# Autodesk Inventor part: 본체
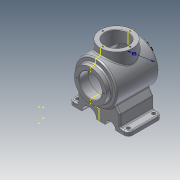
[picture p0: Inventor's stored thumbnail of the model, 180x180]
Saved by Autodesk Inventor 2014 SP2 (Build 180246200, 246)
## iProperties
Created: 2018-08
Part Number: 본체
Material: 알루미늄 6061
Document SubType Name: Modeling
Designer: 거성
Density: 2.71 g/cm^3
Appearance: 알루미늄 - 평지
Mass: 1903.75 g
Surface Area: 1094.31 cm^2
Volume: 702.492 cm^3
Author: 거성
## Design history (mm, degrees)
sketch "스케치1"
  geometry: L1 (0, 60)-(0, -60); L2 (0, 60)-(38, 60); L3 (38, 60)-(38, 48); L4 (38, 48)-(50, 48); L5 (50, 48)-(50, -52); A1 r 232 centre (-11.435, 171.718) between (0, -60) and (50, -52); 2 further points
  constraints: 10 end point, 3 perpendicular, 2 point on circle, 1 centre point, 1 coincident, 1 midpoint, 1 parallel, 1 vertical
  dimensions: "d0" = 120 distance of L1.start L1.end; "d2" = 76 diameter of L3 L1; "d4" = 12 distance of L2.end L3.end; "d22" = 100 distance of L4.end L5.end; "d23" = 232 radius of A1; "d24" = 100 diameter of L5 L1
revolve "회전1" sketch "스케치1" stored, may be unused: angle "d6" = 90 deg
sketch "스케치2" dims "d8" = 65
  geometry: C1 r 38 at (0, 0) reference; C2 r 27 at (0, 0); 2 further points
  constraints: 2 coincident, 2 vertical alignment, 1 centre point, 2 other
  dimensions: "d7" = 54 diameter of C2
extrude "돌출1" cut sketch "스케치2" distance "d9" = 22; taper "d10" = 0 deg
hole "구멍1" sketch "스케치2" diameter "d11" = 3.242; stored, may be unused: countersink angle "d15" = 90 deg, drill point angle "d17" = 118 deg; dims "d12" = 8, "d13" = 4, "d14" = 2, "d16" = 10
node "작업 평면1"
sketch "스케치3"
  geometry: L1 (50, 48)-(50, -52) reference; L2 (-50, -52)-(50, -52) reference; L3 (-50, -52)-(50, -52) reference; L4 (-50, 48)-(-50, -52) reference; L5 (0, -49.674)-(0, 38.326); L6 (0, 38.326)-(40, 38.326); L7 (40, 38.326)-(40, -43.225); A1 r 232 centre (-11.435, 171.718) between (0, -60) and (50, -52) reference; A2 r 232 centre (11.435, 171.718) between (-50, -52) and (0, -60) reference; A3 r 232 centre (-16.787, 181.718) between (0, -49.674) and (40, -43.225); 3 further points
  constraints: 6 end point, 2 point on circle, 1 centre point, 1 coincident, 1 perpendicular
  dimensions: "d89" = 88 distance of L5.start L5.end; "d91" = 232 radius of A3; "d92" = 10 vertical distance of A1.centre A3.centre; "d108" = 80 diameter of L7 L5
  node "투영된 루프1"
node "작업 평면2"
sketch "스케치4" dims "d31" = 65
  geometry: L1 (-50, 48)-(50, 48) reference; C1 r 38 at (0, -2); C2 r 27 at (0, -2); 2 further points
  constraints: 2 centre point, 2 coincident, 1 vertical alignment, 2 other
  dimensions: "d30" = 76 diameter of C1; "d32" = 54 diameter of C2; "d107" = 50 distance from line of L1 C1.centre
extrude "돌출2" join sketch "스케치4" stored distance "d33" = 22; taper "d34" = 0 deg
extrude "돌출3" cut sketch "스케치4" distance "d35" = 50; taper "d36" = 0 deg
hole "구멍2" sketch "스케치4" diameter "d37" = 3.242; stored, may be unused: countersink angle "d41" = 90 deg, drill point angle "d43" = 118 deg; dims "d38" = 8, "d39" = 4, "d40" = 2, "d42" = 10
node "작업 평면3"
sketch "스케치5"
  geometry: L1 (-39.739, -30.345)-(-50, -45); L2 (-50, -45)-(-50, -72); L3 (-50, -72)-(-70, -72); L4 (-70, -72)-(-70, -82); L5 (70, -82)-(70, -72); L6 (70, -72)-(50, -72); L7 (50, -72)-(50, -45); L8 (50, -45)-(39.739, -30.345); L9 (-70, -82)-(-40, -82); L10 (-15, -82)-(5, -82); L11 (40, -82)-(70, -82); C1 r 38 at (0, 0) reference; A1 r 50 centre (0, 0) between (-39.739, -30.345) and (39.739, -30.345) reference; A2 r 12.5 centre (-27.5, -82) between (-15, -82) and (-40, -82); A3 r 17.5 centre (22.5, -82) between (40, -82) and (5, -82); 5 further points
  constraints: 22 end point, 9 perpendicular, 6 point on circle, 3 midpoint, 2 centre point, 2 horizontal alignment, 2 parallel, 1 point on line, 1 vertical, 1 vertical alignment
  dimensions: "d48" = 35 deg angle of L1 L4; "d50" = 20 distance of L2.end L3.end; "d52" = 10 distance of L3.end L4.end; "d61" = 140 distance of L4.end L5.start; "d62" = 20 distance of L5.end L6.end; "d63" = 10 distance of L5.start L5.end; "d64" = 35 deg angle of L5 L8; "d65" = 25 diameter of A2; "d66" = 35 diameter of A3; "d67" = 27.5 distance of point (0, -82) A2.centre; "d68" = 22.5 distance of point (0, -82) A3.centre; "d69" = 27 distance of L1.end L2.end; "d70" = 82 distance from line of C1.centre L9; "d71" = 42.5 distance of L4.end A2.centre; "d72" = 47.5 distance of L5.start A3.centre; "d73" = 22.5 distance of A2.centre point (-5, -82)
extrude "돌출4" join sketch "스케치5" stored distance "d75" = 80; taper "d76" = 0 deg
node "작업 평면4"
fillet "모깎기1" dims "d79" = 3
fillet "모깎기2" dims "d80" = 3
fillet "모깎기3" dims "d81" = 3
fillet "모깎기5" dims "d83" = 10
fillet "모깎기6" dims "d84" = 10
node "작업 평면5"
sketch "스케치7"
  geometry: L1 (38, -38)-(-38, -38) reference; 1 further point
revolve "회전3" stored, may be unused: angle "d93" = 90 deg
fillet "모깎기8" dims "d94" = 3
chamfer "모따기1" distance "d95" = 1; stored, may be unused: second distance "d96" = 2, angle "d97" = 45 deg
node "작업 평면7"
sketch "스케치8"
  geometry: C1 r 4 at (0, 7); C2 r 4 at (0, 67); A1 r 7 centre (0, 67) between (0, 74) and (-7, 67) reference; A2 r 7 centre (0, 7) between (-7, 7) and (0, 0) reference; 1 further point
  constraints: 2 centre point, 2 coincident
  dimensions: "d98" = 8 diameter of C1; "d99" = 8 diameter of C2
extrude "돌출5" cut sketch "스케치8" stored distance "d100" = 80; taper "d101" = 0 deg
node "작업 평면6"
sketch "스케치9"
  geometry: C1 r 4 at (10, -7); C2 r 4 at (10, -67); A1 r 7 centre (10, -67) between (10, -74) and (17, -67) reference; A2 r 7 centre (10, -7) between (17, -7) and (10, 0) reference; 1 further point
  constraints: 2 centre point, 2 coincident
  dimensions: "d102" = 8 diameter of C1; "d103" = 8 diameter of C2
extrude "돌출6" cut sketch "스케치9" distance "d104" = 80; taper "d105" = 0 deg
fillet "모깎기9" dims "d106" = 3
node "작업 평면8"
node "작업 평면9"
sketch "스케치11"
  geometry: L1 (-34.121, 50)-(-32.5, 49.026) reference; L2 (-32.5, 49.026)-(-30.879, 50) reference; L3 (-30.879, 50)-(-30.879, 60) reference; L4 (-30.879, 60)-(-28, 60) reference; L5 (-28, 60)-(-27, 59) reference; L6 (-27, 59)-(-27, 38.326) reference; L7 (-27, 38.326)-(-37, 38.326) reference; L8 (-40, 35.326)-(-40, -40.876) reference; L9 (40, -40.876)-(40, -29) reference; L10 (40, -29)-(64, -29) reference; L11 (64, -29)-(65, -30) reference; L12 (65, -30)-(65, -32.879) reference; L13 (65, -32.879)-(55, -32.879) reference; L14 (55, -32.879)-(54.026, -34.5) reference; L15 (54.026, -34.5)-(55, -36.121) reference; L16 (55, -36.121)-(65, -36.121) reference; L17 (65, -36.121)-(65, -40) reference; L18 (65, -40)-(53, -40) reference; L19 (50, -43)-(50, -49.701) reference; L20 (-50, -49.701)-(-50, -43) reference; L21 (-53, -40)-(-82, -40) reference; L22 (-82, -40)-(-82, 40) reference; L23 (-82, 40)-(-53, 40) reference; L24 (-50, 43)-(-50, 45) reference; L25 (-47, 48)-(-41, 48) reference; L26 (-38, 51)-(-38, 60) reference; L27 (-38, 60)-(-34.121, 60) reference; L28 (-34.121, 60)-(-34.121, 50) reference; L29 (32.5, 49.026)-(34.121, 50) reference; L30 (34.121, 50)-(34.121, 60) reference; L31 (34.121, 60)-(38, 60) reference; L32 (38, 60)-(38, 51) reference; L33 (41, 48)-(47, 48) reference; L34 (50, 45)-(50, 39) reference; L35 (53, 36)-(65, 36) reference; L36 (65, 36)-(65, 32.121) reference; L37 (65, 32.121)-(55, 32.121) reference; L38 (55, 32.121)-(54.026, 30.5) reference; L39 (54.026, 30.5)-(55, 28.879) reference; L40 (55, 28.879)-(65, 28.879) reference; L41 (65, 28.879)-(65, 26) reference; L42 (65, 26)-(64, 25) reference; L43 (64, 25)-(40, 25) reference; L44 (40, 25)-(40, 35.326) reference; L45 (37, 38.326)-(27, 38.326) reference; L46 (27, 38.326)-(27, 59) reference; L47 (27, 59)-(28, 60) reference; L48 (28, 60)-(30.879, 60) reference; L49 (30.879, 60)-(30.879, 50) reference; L50 (30.879, 50)-(32.5, 49.026) reference; L51 (0, 0)-(24.076, -57.548); A1 r 3 centre (-37, 35.326) between (-37, 38.326) and (-40, 35.326) reference; A2 r 3 centre (-37, -40.876) between (-40, -40.876) and (-37.705, -43.792) reference; A3 r 232 centre (16.787, 181.718) between (-37.705, -43.792) and (0, -49.674) reference; A4 r 232 centre (-16.787, 181.718) between (0, -49.674) and (37.705, -43.792) reference; A5 r 3 centre (37, -40.876) between (37.705, -43.792) and (40, -40.876) reference; A6 r 3 centre (47, -49.701) between (47.766, -52.602) and (50, -49.701) reference; A7 r 232 centre (-11.435, 171.718) between (0, -60) and (47.766, -52.602) reference; A8 r 232 centre (11.435, 171.718) between (-47.766, -52.602) and (0, -60) reference; A9 r 3 centre (-47, -49.701) between (-50, -49.701) and (-47.766, -52.602) reference; A10 r 3 centre (-53, -43) between (-50, -43) and (-53, -40) reference; A11 r 3 centre (-53, 43) between (-53, 40) and (-50, 43) reference; A12 r 3 centre (-47, 45) between (-47, 48) and (-50, 45) reference; A13 r 3 centre (-41, 51) between (-41, 48) and (-38, 51) reference; A14 r 3 centre (41, 51) between (38, 51) and (41, 48) reference; A15 r 3 centre (47, 45) between (50, 45) and (47, 48) reference; A16 r 3 centre (37, 35.326) between (40, 35.326) and (37, 38.326) reference
  constraints: 2 end point, 1 point on circle, 2 other
  node "절단 모서리 투영1"
node "작업 평면10"
node "작업 평면11"
sketch "스케치12"
  geometry: C1 r 32.5 at (0, 0); 1 further point
  constraints: 1 centre point, 1 coincident, 1 other
  dimensions: "d113" = 65 diameter of C1
node "솔리드1"
pattern_circular "원형 패턴1" dims angle "d19" = 360 deg
pattern_circular "원형 패턴2" dims angle "d45" = 360 deg
node "투영된 루프2"
other parameters: "d25" = 0, "d29" = 65, "d47" = 0, "d60" = 82, "d86" = 0, "d111" = 0
